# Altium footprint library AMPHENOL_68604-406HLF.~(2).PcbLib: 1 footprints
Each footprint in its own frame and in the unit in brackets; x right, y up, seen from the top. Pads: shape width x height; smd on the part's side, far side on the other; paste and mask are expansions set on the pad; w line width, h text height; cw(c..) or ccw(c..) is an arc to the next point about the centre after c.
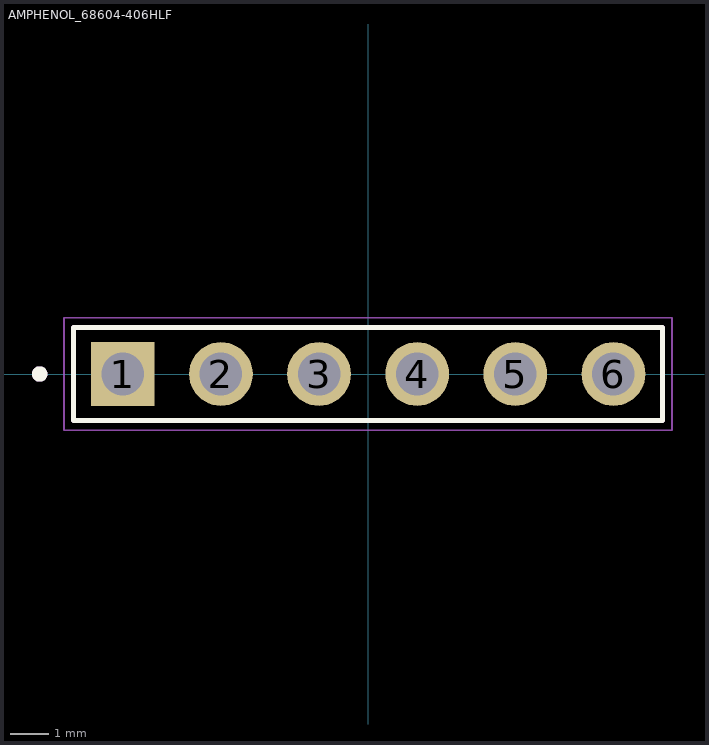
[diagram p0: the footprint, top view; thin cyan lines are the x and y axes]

## AMPHENOL_68604-406HLF [mm] "6 Pin 6Pos THT BergeStick 2.54MM Amphenol 68604-406HLF 3A AMPHENOL_68604-406HLF"
height 12.198
pads (6):
  rect 1.65x1.65 / inner round 1.65 / far side rect 1.65x1.65 hole 1.1: 1(-6.35,0)
  round 1.65 hole 1.1: 2(-3.81,0) 3(-1.27,0) 4(1.27,0) 5(3.81,0) 6(6.35,0)
Top Overlay:
  circle w0.2: c-8.5,0 r0.1
  lines w0.127: -7.62,-1.205 -7.62,1.205 7.62,1.205 7.62,-1.205 -7.62,-1.205
Mechanical 13:
  circle w0.2: c-8.5,0 r0.1
  lines w0.127: -7.62,-1.205 -7.62,1.205 7.62,1.205 7.62,-1.205 -7.62,-1.205
Mechanical 15:
  lines w0.05: -7.87,-1.455 7.87,-1.455 7.87,1.455 -7.87,1.455 -7.87,-1.455
3D body "step_temp.STEP": height 12.19, standoff -3.05, extent -7.62,-1.205 7.62,1.205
